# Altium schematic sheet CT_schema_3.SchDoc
size 309 x 315 mm
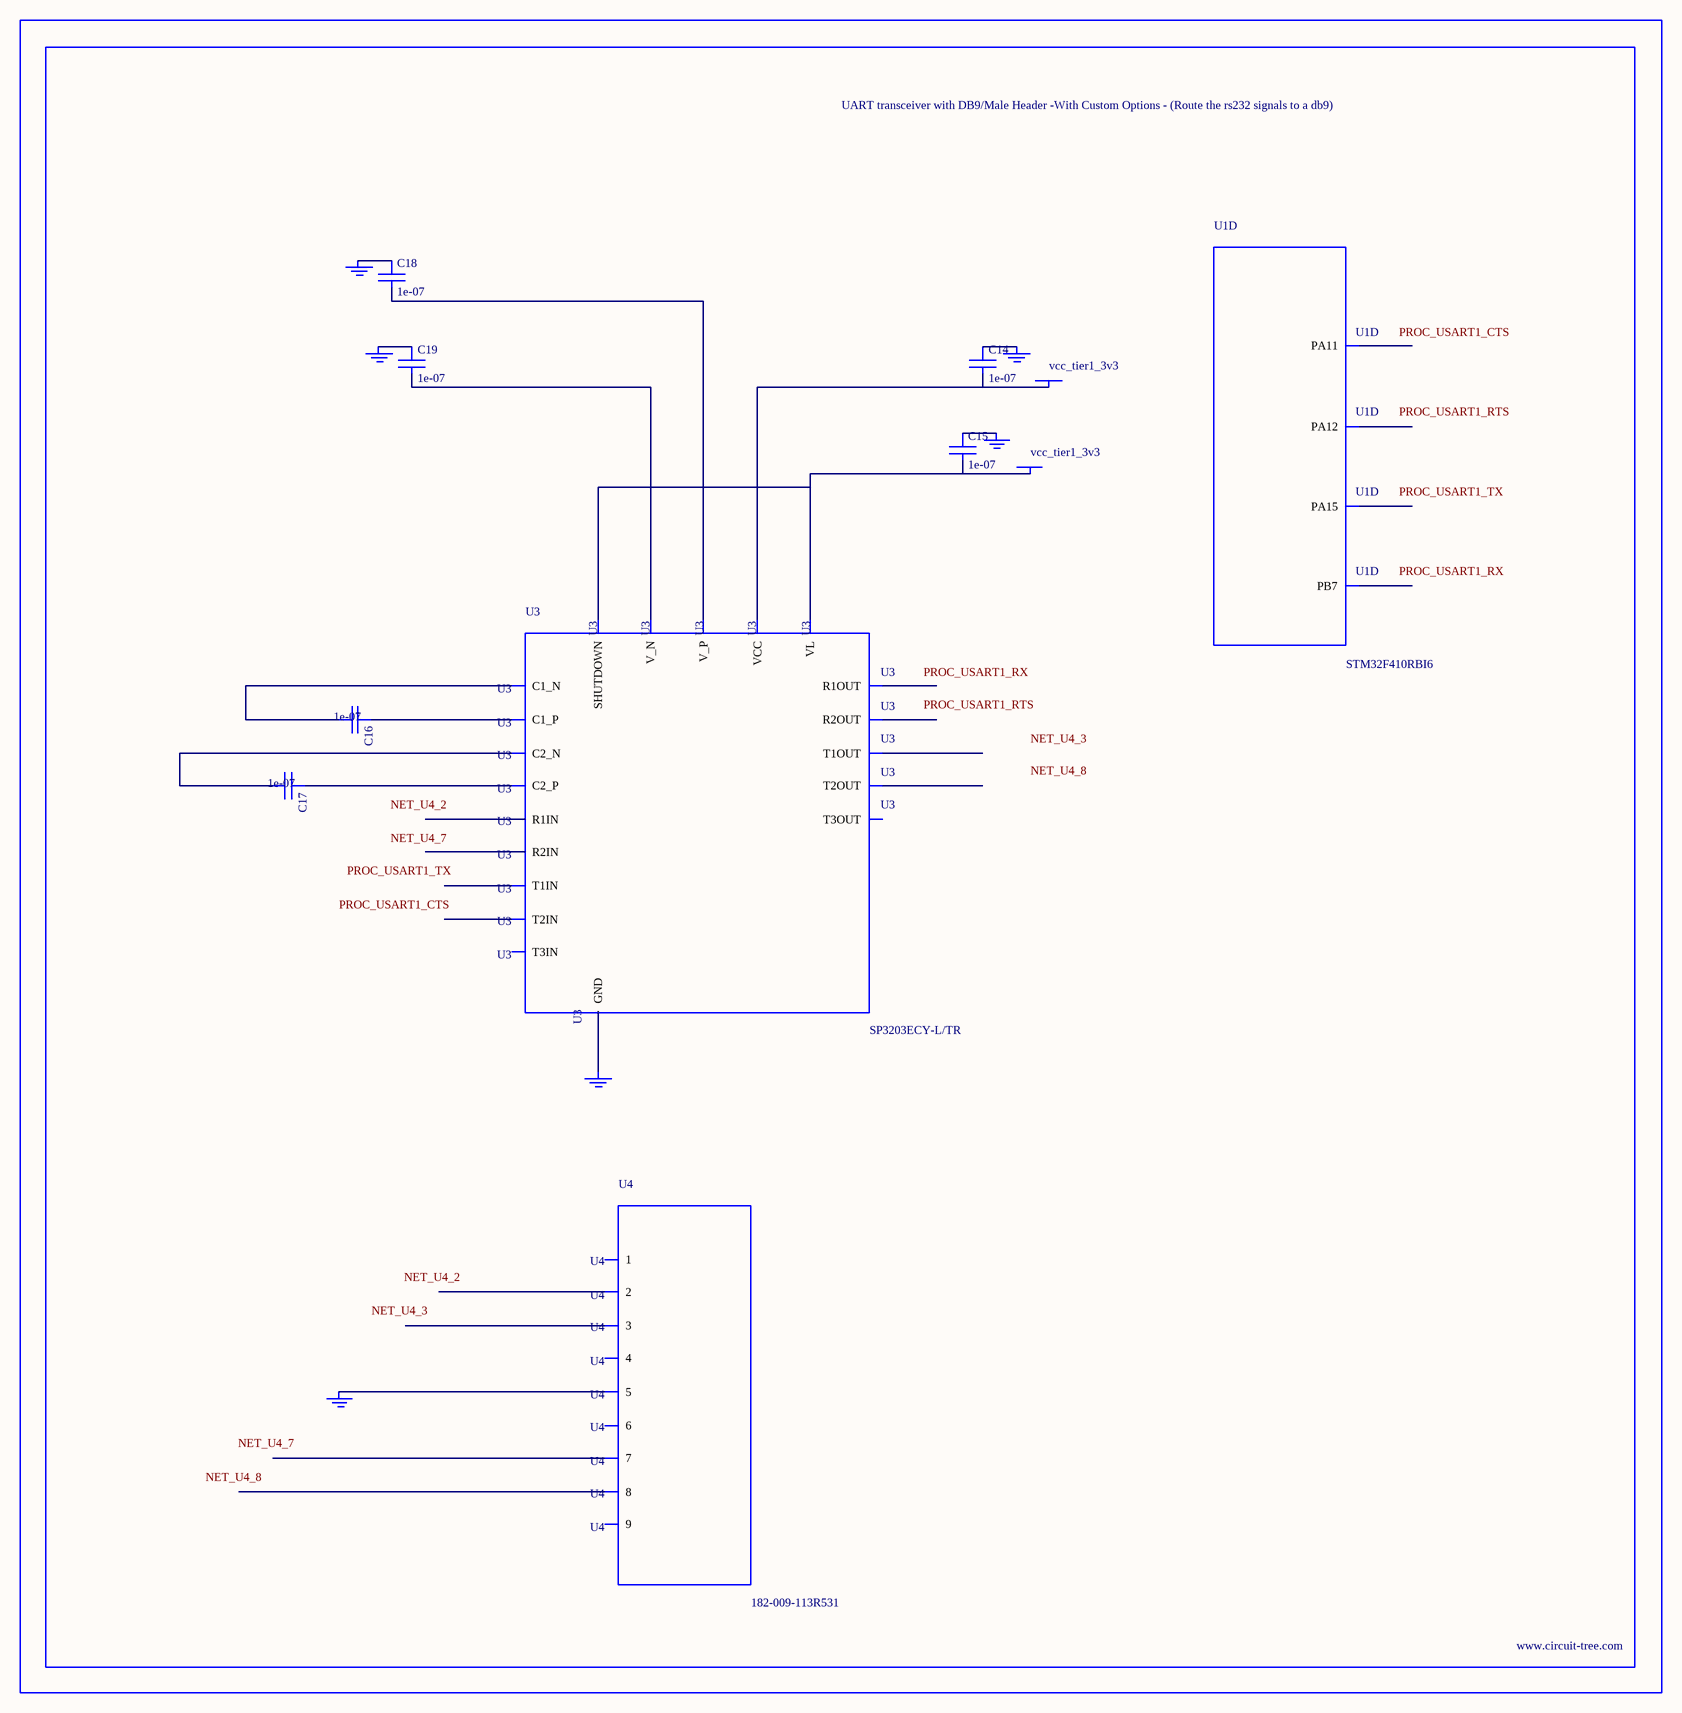
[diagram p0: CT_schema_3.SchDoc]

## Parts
BORDER2  (no value)
C14  1e-07  [C0402]
C15  1e-07  [C0402]
C16  1e-07  [C0402]
C17  1e-07  [C0402]
C18  1e-07  [C0402]
C19  1e-07  [C0402]
GND_INSTANCE_2_0  (no value)
GND_INSTANCE_2_1  (no value)
GND_INSTANCE_2_2  (no value)
GND_INSTANCE_2_3  (no value)
GND_INSTANCE_2_4  (no value)
GND_INSTANCE_2_5  (no value)
POWER_INSTANCE_2_0  vcc_tier1_3v3
POWER_INSTANCE_2_1  vcc_tier1_3v3
U1  STM32F410RBI6  [UFBGA64]  (part D of 6)
U3  SP3203ECY-L/TR  [TSSOP20-I]
U4  182-009-113R531  [182-009-MALE]

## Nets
NetC14_1: C14.1 GND_INSTANCE_2_3.0(GND)
NetC14_2: C14.2 POWER_INSTANCE_2_1.0(PWR) U3.19(VCC)
NetC15_1: C15.1 GND_INSTANCE_2_2.0(GND)
NetC15_2: C15.2 POWER_INSTANCE_2_0.0(PWR) U3.12(VL) U3.20(SHUTDOWN)
NetC16_1: C16.1 U3.1(C1_P)
NetC16_2: C16.2 U3.3(C1_N)
NetC17_1: C17.1 U3.4(C2_P)
NetC17_2: C17.2 U3.5(C2_N)
NetC18_1: C18.1 GND_INSTANCE_2_0.0(GND)
NetC18_2: C18.2 U3.2(V_P)
NetC19_1: C19.1 GND_INSTANCE_2_1.0(GND)
NetC19_2: C19.2 U3.6(V_N)
NetGND_INSTANCE_2_4_0: GND_INSTANCE_2_4.0(GND) U3.18(GND)
NetGND_INSTANCE_2_5_0: GND_INSTANCE_2_5.0(GND) U4.5

Not connected (* = marked no-connect by the designer): U1 A7(PA15) A8(PA12) B4(PB7) D7(PA11); U3 7(T1IN) 8(T2IN) 9(T3IN) 10(R2OUT) 11(R1OUT) 13(R2IN) 14(R1IN) 15(T3OUT) 16(T2OUT) 17(T1OUT); U4 1 2 3 4 6 7 8 9

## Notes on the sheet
- Labels drawn without touching a wire or pin: NET_U4_2, NET_U4_3, NET_U4_7, NET_U4_8, PROC_USART1_CTS, PROC_USART1_RTS, PROC_USART1_RX, PROC_USART1_TX

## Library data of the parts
BORDER2 = BORDER_PAGE2
C14-C19 = C0402C104K3RACTU
GND_INSTANCE_2_0-GND_INSTANCE_2_5 = GND
POWER_INSTANCE_2_0 POWER_INSTANCE_2_1 = PWR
